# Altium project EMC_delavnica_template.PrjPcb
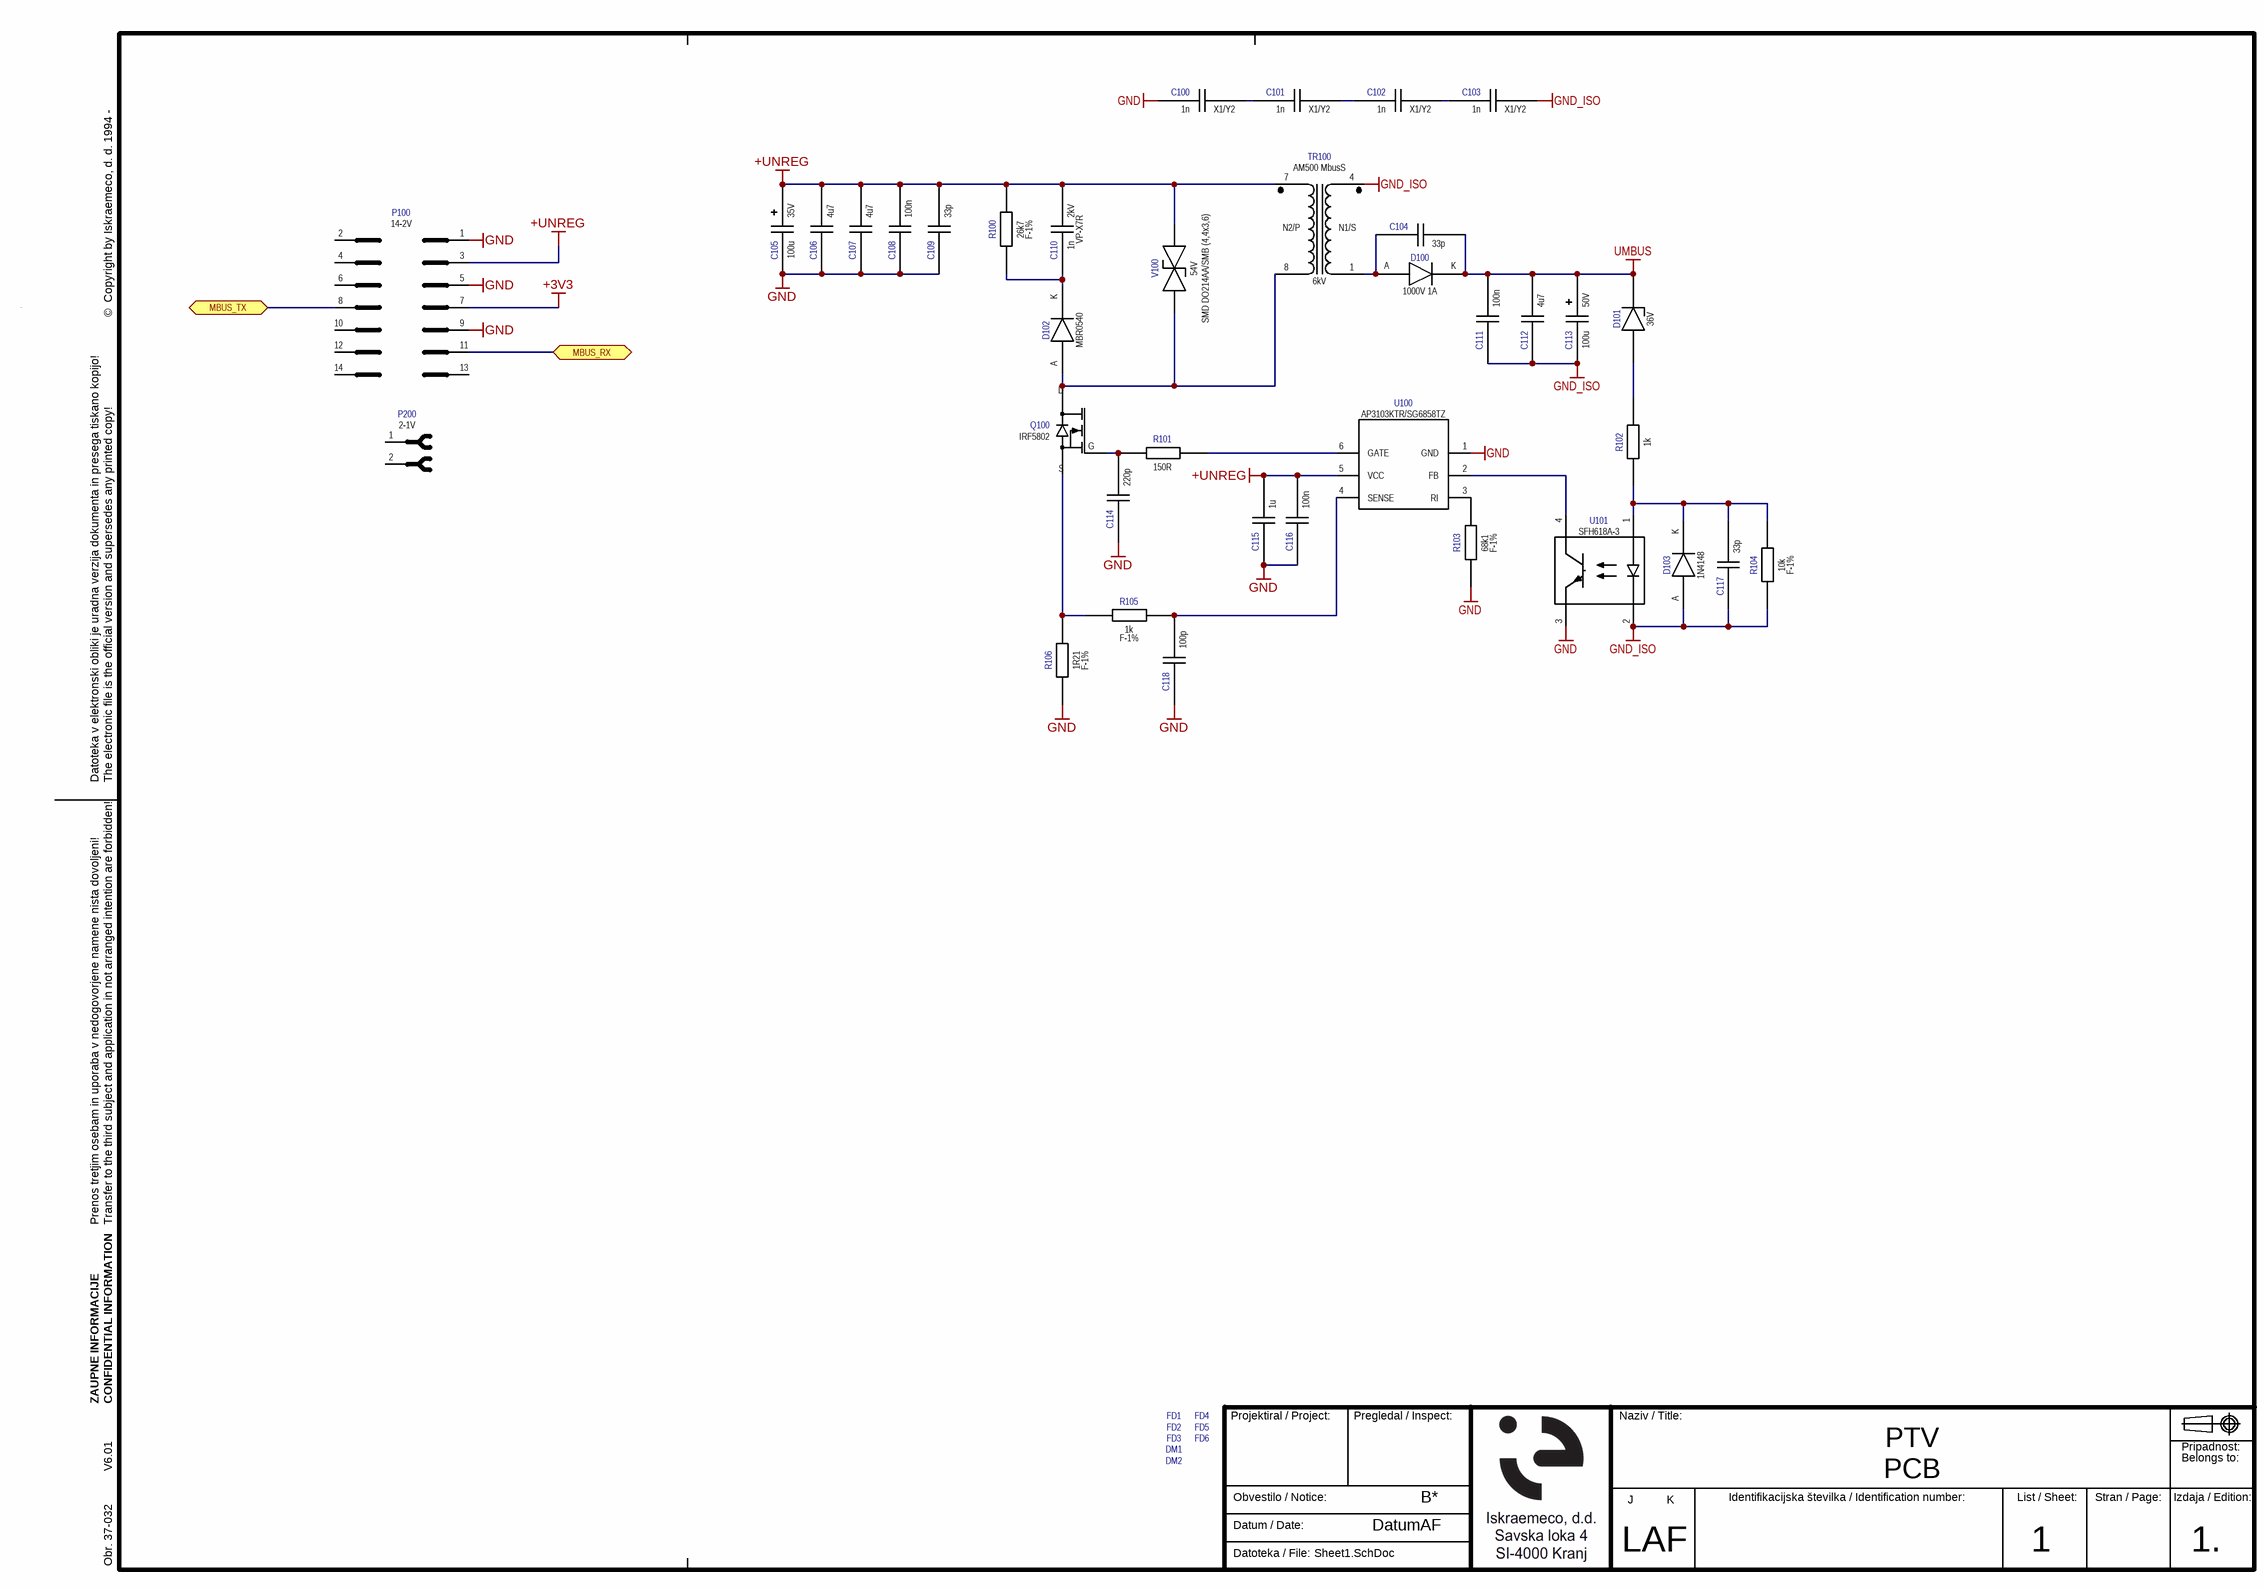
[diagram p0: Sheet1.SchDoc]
VersionSCH: 01; VersionPCB: A; TitlePCB: PCB; TitleAPCB: APCB; ScaleAW: x:x; ScaleAH: x:x; OPTV_prefix: 028640; NTIV: NTIV/XY; Notice: B*; NazivPTV: PTV; NazivOPTV: OPTV; ID_prefix028: 028.640; ID_prefix: 027.640; ID_code: ___; Edition_Infor_BOM: 1.; EditionTB: 1.; EditionAW_2: 1.; EditionAW_1: 1.; EditionAH: 1.; EditionAF: 1.; DatumTB: DatumTB; DatumPCB: DatumPCB; DatumAW_2: DatumAW_2; DatumAW_1: DatumAW_1; DatumAH: DatumAH; DatumAF: DatumAF
2 sheets, 45 parts. Net scope: flat (ports and power ports of the same name join across sheets).
Board file: EMC_delavnica_template.PcbDoc
Sheets:
  Sheet1.SchDoc
  Sheet2.SchDoc

## Sheet Sheet1.SchDoc
size A3; Organization: Altium Limited; DocumentNumber: 1; SheetNumber: 1; SheetTotal: 2; Sheet: 1; Page: 1+; VersionSCH_local: 01; Scale: X*; J K: LAF; Identification number: 028.640.___.000; ID+Version: 028.640.___.000-A01

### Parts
C100  value 1n  Type: X1/Y2  [CAPC4520]  (hidden comment: 613070511000)
C101  value 1n  Type: X1/Y2  [CAPC4520]  (hidden comment: 613070511000)
C102  value 1n  Type: X1/Y2  [CAPC4520]  (hidden comment: 613070511000)
C103  value 1n  Type: X1/Y2  [CAPC4520]  (hidden comment: 613070511000)
C104  value 33p  [CAPC1005]  (hidden comment: 613070392000)
C105  value 100u  VOLTAGE: 35V  [CAPAE83W105H]  (hidden comment: 614000031000)
C106  value 4u7  [CAPC3216]  (hidden comment: 613070488000)
C107  value 4u7  [CAPC3216]  (hidden comment: 613070488000)
C108  value 100n  [CAPC1005]  (hidden comment: 613070438000)
C109  value 33p  [CAPC1005]  (hidden comment: 613070392000)
C110  value 1n  VOLTAGE: 2kV  TYPE: VP-X7R  [CAPC3216]  (hidden comment: 613070323000)
C111  value 100n  [CAPC1005]  (hidden comment: 613070438000)
C112  value 4u7  [CAPC3216]  (hidden comment: 613070488000)
C113  value 100u  VOLTAGE: 50V  [CAPAE83W105H]  (hidden comment: 614000032000)
C114  value 220p  [CAPC1005]  (hidden comment: 613070346000)
C115  value 1u  [CAPC3225]  (hidden comment: 613070255000)
C116  value 100n  [CAPC1005]  (hidden comment: 613070438000)
C117  value 33p  [CAPC1005]  (hidden comment: 613070392000)
C118  value 100p  [CAPC1005]  (hidden comment: 613070393000)
D100  value 1000V 1A  [DIOSMDO214AC]  (hidden comment: 623007589000)
D101  value 36V  [DIOSOD323]  (hidden comment: 623005265000)
D102  value MBR0540  [TVSDO219AB]  (hidden comment: 623007586000)
D103  value 1N4148  [DIOSOD323]  (hidden comment: 623007671000)
DM1  TIV-DATAMATRIX_11X11  [TIV-DATAMATRIX_11x11]  (value not drawn)
DM2  TIV-DATAMATRIX_11X11  [TIV-DATAMATRIX_11x11]  (value not drawn)
FD1  TIV-FID15X30  [TIV-FID15X30]  (value not drawn)
FD2  TIV-FID15X30  [TIV-FID15X30]  (value not drawn)
FD3  TIV-FID15X30  [TIV-FID15X30]  (value not drawn)
FD4  TIV-FID15X30  [TIV-FID15X30]  (value not drawn)
FD5  TIV-FID15X30  [TIV-FID15X30]  (value not drawn)
FD6  TIV-FID15X30  [TIV-FID15X30]  (value not drawn)
P100  value 14-2V  [CON_G08PTIV_14-2V]  (hidden comment: 027901066000)
P200  value 2-1V  [CON_AK104-DS_2-1V]  (hidden comment: 631000042000)
Q100  value IRF5802  [SOT23-6]  (hidden comment: 623004147000)
R100  value 26k7  TOLERANCE: F-1%  [RESMELF3516]  (hidden comment: 610422823000)
R101  value 150R  [RESC1005]  (hidden comment: 610426055000)
R102  value 1k  [RESC1005]  (hidden comment: 610426100000)
R103  value 68k1  TOLERANCE: F-1%  [RESC1005]  (hidden comment: 610427445000)
R104  value 10k  TOLERANCE: F-1%  [RESC1005]  (hidden comment: 610427132000)
R105  value 1k  TOLERANCE: F-1%  [RESC1005]  (hidden comment: 610427100000)
R106  value 1R21  TOLERANCE: F-1%  [RESMELF3516]  (hidden comment: 610422969000)
TR100  value AM500 MbusS  [XFMR_E13X20-4_9P-ZA_V1]  (hidden comment: 662000266000)
U100  value AP3103KTR/SG6858TZ  [SOT23-6]  (hidden comment: 665150862000)
U101  value SFH618A-3  [OPTODIP4-SMD8]  (hidden comment: 623010015000)
V100  value 54V  PACKAGE: SMD DO214AA/SMB (4,4x3,6)  [TVSDO214AA-5.6X4]  (hidden comment: 619000024000)

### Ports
MBUS_RX (bidir), MBUS_TX (bidir)

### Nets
+3V3: P100.7
+UNREG: C105.2 C106.2 C107.2 C108.2 C109.2 C110.2 C115.2 C116.2 P100.3 R100.2 TR100.7 U100.5(VCC) V100.2
GND: C100.1 C105.1 C106.1 C107.1 C108.1 C109.1 C114.1 C115.1 C116.1 C118.1 P100.1 P100.5 P100.9 R103.1 R106.1 U100.1(GND) U101.3(E)
GND_ISO: C103.2 C111.1 C112.1 C113.1 C117.1 D103.2 R104.1 TR100.4 U101.2(K)
UMBUS: C104.2 C111.2 C112.2 C113.2 D100.1 D101.1
MBUS_RX: P100.11 ; port MBUS_RX
MBUS_TX: P100.8 ; port MBUS_TX
NetC100_2: C100.2 C101.1
NetC101_2: C101.2 C102.1
NetC102_2: C102.2 C103.1
NetC104_1: C104.1 D100.2 TR100.1
NetC110_1: C110.1 D102.1 R100.1
NetC114_2: C114.2 Q100.3(G) R101.1
NetC117_2: C117.2 D103.1 R102.1 R104.2 U101.1(A)
NetC118_2: C118.2 R105.2 U100.4(SENSE)
NetD101_2: D101.2 R102.2
NetD102_2: D102.2 Q100.1(D) Q100.2(D) Q100.5(D) Q100.6(D) TR100.8 V100.1
NetQ100_4: Q100.4(S) R105.1 R106.2
NetR101_2: R101.2 U100.6(GATE)
NetR103_2: R103.2 U100.3(RI)
NetU100_2: U100.2(FB) U101.4(C)

Not connected (* = marked no-connect by the designer): P100 2 4 6 10 12 13 14; P200 1 2

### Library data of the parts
C100-C103 = 613070511000-4: CAPACITOR; Part Group: 02_KONDENZATORJI; PART NAME: KOND X1/Y2 1808*1n 250V M; Tolerance: M-20%; Internal standard: ZS-K.02.140.08; MOUNTING_TYPE: SMD; Voltage: 250V
C104 C109 C117 = 613070392000-4: CAPACITOR; PART NAME: KOND VP 0402 NP0*33p 50V J; Part Group: 02_KONDENZATORJI; Voltage: 50V; Internal standard: ZS-K.02.200.25; Tolerance: J-5%; MOUNTING_TYPE: SMD; Type: VP-NP0
C105 = 614000031000-7: CAPACITOR polarized; PART NAME: KOND AL-SMD*100my 35V M; Part Group: 02_KONDENZATORJI; Internal standard: ZS-K.02.142.08; Tolerance: M-20%; MOUNTING_TYPE: SMD; Type: AL-SMDLILL
C106 C107 C112 = 613070488000-4: CAPACITOR; Part Group: 02_KONDENZATORJI; PART NAME: KOND VP 1206 X7R*4,7my 50V K; MOUNTING_TYPE: SMD; Voltage: 50V; Internal standard: ZS-K.02.201.37; Type: VP-X7R; Tolerance: K-10%
C108 C111 C116 = 613070438000-4: CAPACITOR; Part Group: 02_KONDENZATORJI; PART NAME: KOND VP 0402 X7R*100n 50V K; Tolerance: K-10%; MOUNTING_TYPE: SMD; Voltage: 50V; Internal standard: ZS-K.02.201.41; Type: VP-X7R
C110 = 613070323000-4: CAPACITOR voltage type; PART NAME: KOND VP 1206 X7R*1n 2kV K; Part Group: 02_KONDENZATORJI; Internal standard: ZS-K.02.201.43; Tolerance: K-10%; MOUNTING_TYPE: SMD
C113 = 614000032000-7: CAPACITOR polarized; Part Group: 02_KONDENZATORJI; PART NAME: KOND AL-SMD*100my 50V M; Internal standard: ZS-K.02.142.08; Tolerance: M-20%; Type: AL-SMDLILL; MOUNTING_TYPE: SMD
C114 = 613070346000-4: CAPACITOR; Part Group: 02_KONDENZATORJI; PART NAME: KOND VP 0402 NP0*220p 50V J; Voltage: 50V; Tolerance: J-5%; MOUNTING_TYPE: SMD; Internal standard: ZS-K.02.200.25; Type: VP-NP0
C115 = 613070255000-4: CAPACITOR; Part Group: 02_KONDENZATORJI; PART NAME: KOND VP 1210 X7R*1my 50V K; Tolerance: K-10%; Internal standard: ZS-K.02.201.39; MOUNTING_TYPE: SMD; Type: VP-X7R; Voltage: 50V
C118 = 613070393000-4: CAPACITOR; PART NAME: KOND VP 0402 NP0*100p 50V J; Part Group: 02_KONDENZATORJI; MOUNTING_TYPE: SMD; Type: VP-NP0; Tolerance: J-5%; Voltage: 50V; Internal standard: ZS-K.02.200.25
D100 = 623007589000-5: DIODE; PART NAME: DIODA-U FUF1*1000V 1A; Part Group: 06_DIODE; Internal standard: ZS-K.06.212.07; Type: FUF1M; Voltage: 1000V; MOUNTING_TYPE: SMD
D101 = 623005265000-5: DIODE Zener; PART NAME: DIODA-Z BZX*36V J; Part Group: 06_DIODE; Tolerance: J-5%; Type: BZX384; Internal standard: ZS-K.06.171.05; MOUNTING_TYPE: SMD
D102 = 623007586000-5: DIODE; Part Group: 06_DIODE; PART NAME: DIODA-SCH MBR0540*40V 0,5A; Voltage: 40V; MOUNTING_TYPE: SMD; Internal standard: ZS-K.06.244.03
D103 = 623007671000-6: DIODE; PART NAME: DIODA-ST 1N4148*75V 150mA; Part Group: 06_DIODE; Internal standard: ZS-K.06.106.17; Voltage: 75V; MOUNTING_TYPE: SMD; Type: DIODA-ST
DM1 DM2 = TIV-DATAMATRIX_11X11-4: Datamatrix; Part Group: OSTALO; Internal standard: ISKRAEMECO
FD1-FD6 = TIV-FID15X30-5: Fiducial; Part Group: OSTALO; Internal standard: ISKRAEMECO
P100 = 027901066000-5: Connector 14-2m; PART NAME: VTIC G08 5,8*14-2 V; Part Group: 27_KODA; Internal standard: W27.901.060; MOUNTING_TYPE: THT
P200 = 631000042000-5: Connector 2-1f; Part Group: 31_KONEKTORJI; PART NAME: SPONKA AK104-DS*2-1 V; Internal standard: ZS-K.31.181.35; MOUNTING_TYPE: THT
Q100 = 623004147000-6: MOSFET N Channel; Part Group: 07_TRANZISTORJI; PART NAME: TRANZISTOR MF-N*IRF5802; Type: MOSFET-SPMS; Internal standard: ZS-K.07.372.01; MOUNTING_TYPE: SMD
R100 = 610422823000-4: RESISTOR TOL; PART NAME: UPOR MPL SOD80*26,7K F 50; Part Group: 03_UPORI; Voltage: 200V; Internal standard: ZS-K.03.140.19; MOUNTING_TYPE: SMD
R101 = 610426055000-3: RESISTOR; PART NAME: UPOR DPL 0402*150R J 250; Part Group: 03_UPORI; Voltage: 25V; MOUNTING_TYPE: SMD; Internal standard: ZS-K.03.146.06; Tolerance: J-5%
R102 = 610426100000-3: RESISTOR; Part Group: 03_UPORI; PART NAME: UPOR DPL 0402*1K J 250; Internal standard: ZS-K.03.146.06; Voltage: 25V; MOUNTING_TYPE: SMD; Tolerance: J-5%
R103 = 610427445000-3: RESISTOR TOL; PART NAME: UPOR DPL 0402*68,1K F 100; Part Group: 03_UPORI; Voltage: 25V; MOUNTING_TYPE: SMD; Internal standard: ZS-K.03.146.08
R104 = 610427132000-3: RESISTOR TOL; PART NAME: UPOR DPL 0402*10K F 100; Part Group: 03_UPORI; Internal standard: ZS-K.03.146.08; MOUNTING_TYPE: SMD; Voltage: 25V
R105 = 610427100000-3: RESISTOR TOL; Part Group: 03_UPORI; PART NAME: UPOR DPL 0402*1K F 100; Internal standard: ZS-K.03.146.08; Voltage: 25V; MOUNTING_TYPE: SMD
R106 = 610422969000-5: RESISTOR TOL; Part Group: 03_UPORI; PART NAME: UPOR MPL 0204*1,21R F 50; Internal standard: ZS-K.03.140.19; Voltage: 200V; MOUNTING_TYPE: SMD
TR100 = 662000266000-6: TRAFO STIK*AM500 MbusS; Part Group: 36_TRANSFORMATORJI; Type: STIKALNI; MOUNTING_TYPE: THT; Internal standard: ZS-K.36.155.67
U100 = 665150862000-6: VEZJE NADZ PWM - AP3103; PART NAME: VEZJE NADZ PWM 6858*I; Part Group: 09_INTEGRIRANA_VEZJA; MOUNTING_TYPE: SMD; Internal standard: ZS-K.09.398.12
U101 = 623010015000-5: OPTOSKLOPNIK 4PIN; PART NAME: OPTOSKLOPNIK SFH618A-3; Part Group: 08_OPTOELEMENTI; Internal standard: ZS-K.08.192.12; MOUNTING_TYPE: SMD
V100 = 619000024000-5: Transzorb 2way; PART NAME: TRANSZORB 2-S*SMBJ 54V A; Part Group: 05_VARISTORJI; MOUNTING_TYPE: SMD; Internal standard: ZS-K.05.124.13

## Sheet Sheet2.SchDoc
size A3; Scale: X*; Organization: Iskraemeco; DocumentNumber: 2; SheetNumber: 2; SheetTotal: 2; Sheet: 1; Page: 2; VersionSCH_local: 01; J K: LAF; Identification number: 028.640.___.000; ID+Version: 028.640.___.000-A01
